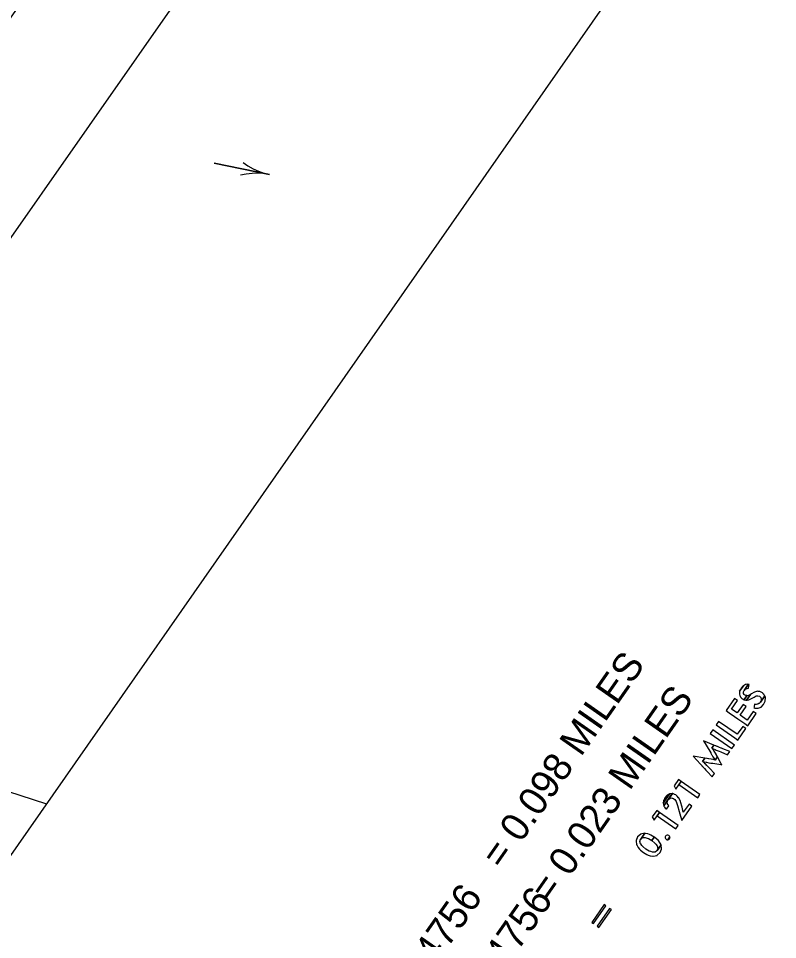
# Model space of a CAD drawing. Extents: x 1731327 to 1735374, y 884856 to 889832.
# Drawn here: x 1732222.4 to 1732491.1, y 885272.3 to 885598.5 of the extents above; entities that cross this region are included whole.
import ezdxf

# ---------------------------------------------------------------- set-up
doc = ezdxf.new("R2010")
doc.units = 0
for name, color, linetype in [('COGO Default Chain', 7, 'Continuous'), ('Exist Other Culture Area Outline', 7, 'Continuous'), ('Exist Other Culture Sign Text', 7, 'Continuous'), ('Exist Property Iron Pin CELL', 7, 'Continuous'), ('Exist Structure Minor Pipes RCP 24 Inch', 7, 'Continuous')]:
    doc.layers.add(name, color=color, linetype=linetype)

# ---------------------------------------------------------------- blocks, each defined once
blk = doc.blocks.new('EXIST HYDRO RIVER FLOW ARROW')
at = {"layer": 'COGO Default Chain'}
blk.add_line((0, 0), (0, 0), dxfattribs=at)
blk.add_lwpolyline([(0, 0.04575), (0.03775, 0.03), (0.07725, 0.01725), (0.118, 0.00775), (0.159, 0.0015), (0.2, 0), (-0.2, 0), (0.2, 0), (0.159, -0.0015), (0.118, -0.00775), (0.07725, -0.01725), (0.03775, -0.03), (0, -0.04575)], dxfattribs=at)

msp = doc.modelspace()

# ---------------------------------------------------------------- linework, layer by layer
at = {"layer": 'Exist Other Culture Area Outline'}
msp.add_lwpolyline([(1732238.91, 886072.74), (1731769.46, 885400.02), (1732118.14, 885156.7), (1732587.59, 885829.41)], close=True, dxfattribs=at)
at = {"layer": 'Exist Other Culture Sign Text'}
msp.add_lwpolyline([(1731775.28, 885408.36), (1732121.12, 885356.5), (1732232.4, 885320.42)], dxfattribs=at)
at = {"layer": 'Exist Property Iron Pin CELL'}
for points in [[(1732478.92, 885357.42), (1732479.22, 885357.24), (1732480.23, 885358.7), (1732479.83, 885358.73), (1732479.39, 885359), (1732479.36, 885359.02), (1732479.28, 885359.13), (1732479.08, 885359.43), (1732479.06, 885359.6), (1732479.04, 885359.85), (1732479.03, 885359.96), (1732479.05, 885360.03), (1732479.14, 885360.26), (1732479.25, 885360.55), (1732480.74, 885362.68), (1732480.56, 885362.71), (1732479.94, 885362.63), (1732479.79, 885362.62), (1732479, 885362.19), (1732477.67, 885360.28), (1732477.61, 885359.49), (1732477.59, 885359.27), (1732477.78, 885358.72), (1732477.84, 885358.53), (1732477.87, 885358.44), (1732477.9, 885358.37), (1732477.91, 885358.35), (1732477.96, 885358.29), (1732478.06, 885358.17), (1732478.14, 885358.08), (1732478.37, 885357.81), (1732478.45, 885357.71), (1732478.47, 885357.69)], [(1732477.72, 885360.39), (1732477.67, 885360.29), (1732479, 885362.19), (1732478.97, 885362.17), (1732478.17, 885361.32), (1732478.17, 885361.32)], [(1732480.38, 885361.29), (1732480.81, 885361.32), (1732480.91, 885362.05), (1732480.94, 885362.3), (1732480.99, 885362.64), (1732480.91, 885362.65), (1732480.89, 885362.66), (1732480.82, 885362.67), (1732480.74, 885362.68), (1732479.25, 885360.55), (1732479.69, 885361.05), (1732479.8, 885361.09), (1732479.83, 885361.1), (1732479.96, 885361.16), (1732480.23, 885361.28)], [(1732479.83, 885357.14), (1732480.05, 885357.1), (1732481.49, 885359.16), (1732481.07, 885358.9), (1732480.42, 885358.69), (1732480.24, 885358.7), (1732479.22, 885357.24), (1732479.39, 885357.21)], [(1732485.31, 885356.99), (1732485.05, 885356.45), (1732486.55, 885358.6), (1732486.51, 885358.71), (1732486.5, 885358.72), (1732486.49, 885358.74), (1732486.41, 885358.95), (1732486.36, 885359.01), (1732486.32, 885359.05), (1732486.12, 885359.25), (1732486.04, 885359.34), (1732485.98, 885359.41), (1732485.73, 885359.68), (1732485.53, 885359.78), (1732485.07, 885360.04), (1732484.86, 885360.16), (1732484.65, 885360.17), (1732484.24, 885360.21), (1732484.24, 885360.21), (1732483.92, 885360.24), (1732483.63, 885360.15), (1732482.93, 885359.94), (1732482.73, 885359.84), (1732481.9, 885359.4), (1732481.49, 885359.16), (1732480.05, 885357.1), (1732480.33, 885357.15), (1732480.93, 885357.25), (1732481.11, 885357.34), (1732481.93, 885357.71), (1732482.29, 885357.91), (1732482.85, 885358.22), (1732483.54, 885358.59), (1732483.8, 885358.63), (1732484.12, 885358.68), (1732484.65, 885358.52), (1732484.82, 885358.38), (1732485.09, 885358.14), (1732485.14, 885358.05), (1732485.2, 885357.93), (1732485.34, 885357.65), (1732485.34, 885357.55), (1732485.33, 885357.41), (1732485.32, 885357.07), (1732485.32, 885357.02)], [(1732479.47, 885348.82), (1732480.59, 885348.04), (1732483.58, 885352.33), (1732482.46, 885353.11), (1732480.33, 885350.06), (1732477.85, 885351.79), (1732479.98, 885354.84), (1732478.89, 885355.6), (1732476.76, 885352.56), (1732474.84, 885353.89), (1732476.97, 885356.94), (1732475.9, 885357.68), (1732472.91, 885353.4), (1732473.98, 885352.65), (1732475.89, 885351.31), (1732476.99, 885350.55)], [(1732485.25, 885354.66), (1732486.16, 885355.6), (1732486.75, 885356.8), (1732486.75, 885356.81), (1732486.79, 885357.88), (1732486.79, 885358.01), (1732486.55, 885358.6), (1732485.05, 885356.45), (1732484.57, 885355.93), (1732484.55, 885355.92), (1732484.51, 885355.9), (1732484.15, 885355.71), (1732484.01, 885355.64), (1732483.93, 885355.63), (1732483.58, 885355.6), (1732483.42, 885355.59), (1732483.33, 885355.61), (1732482.96, 885355.7), (1732482.82, 885354.89), (1732482.78, 885354.66), (1732482.73, 885354.39), (1732483.01, 885354.3), (1732483.06, 885354.29), (1732483.14, 885354.26), (1732483.33, 885354.21), (1732483.36, 885354.21), (1732483.36, 885354.21), (1732483.49, 885354.21), (1732484.14, 885354.22), (1732484.23, 885354.22), (1732485.24, 885354.65)], [(1732475.95, 885343.78), (1732477.07, 885342.99), (1732479.88, 885347.03), (1732478.76, 885347.81), (1732476.81, 885345.02), (1732470.25, 885349.6), (1732469.39, 885348.35)], [(1732467.27, 885345.32), (1732474.95, 885339.96), (1732475.82, 885341.21), (1732468.14, 885346.56)], [(1732468.61, 885336.44), (1732468.98, 885335.9), (1732469.8, 885337.08), (1732469.47, 885337.67), (1732469.47, 885337.67), (1732469.47, 885337.69), (1732469.11, 885338.32), (1732468.7, 885339.06), (1732468.7, 885339.07), (1732468.69, 885339.08), (1732468.64, 885339.15), (1732468.34, 885339.64), (1732468.32, 885339.66), (1732468.32, 885339.66), (1732468.3, 885339.68), (1732467.88, 885340.16), (1732468.6, 885341.19), (1732464.94, 885342.66), (1732467.08, 885339.02), (1732467.43, 885338.43), (1732467.44, 885338.41), (1732467.45, 885338.4), (1732467.46, 885338.38), (1732467.75, 885337.88), (1732467.8, 885337.8), (1732467.81, 885337.79), (1732467.81, 885337.79), (1732468.23, 885337.07), (1732468.61, 885336.45)], [(1732470.98, 885338.77), (1732473.42, 885337.77), (1732474.23, 885338.93), (1732471.78, 885339.91), (1732471.2, 885340.15), (1732471.19, 885340.15), (1732471.19, 885340.15), (1732470.56, 885340.4), (1732469.84, 885340.69), (1732469.84, 885340.69), (1732469.82, 885340.7), (1732469.74, 885340.73), (1732469.24, 885340.93), (1732469.22, 885340.94), (1732469.21, 885340.94), (1732469.19, 885340.95), (1732468.6, 885341.19), (1732467.88, 885340.16), (1732468.44, 885339.87), (1732468.46, 885339.86), (1732468.46, 885339.86), (1732468.48, 885339.85), (1732468.96, 885339.61), (1732469.04, 885339.58), (1732469.05, 885339.57), (1732469.05, 885339.57), (1732469.77, 885339.27), (1732470.39, 885339.02), (1732470.41, 885339.01)], [(1732466.17, 885331.88), (1732467.95, 885329.93), (1732468.75, 885331.08), (1732466.96, 885333.01), (1732466.54, 885333.47), (1732466.53, 885333.48), (1732466.53, 885333.48), (1732466.07, 885333.97), (1732465.55, 885334.54), (1732465.54, 885334.55), (1732465.54, 885334.55), (1732465.47, 885334.61), (1732465.1, 885334.99), (1732465.08, 885335.01), (1732465.07, 885335.01), (1732465.05, 885335.02), (1732464.57, 885335.42), (1732465.4, 885336.6), (1732461.21, 885337.33), (1732463.87, 885334.41), (1732464.3, 885333.94), (1732464.31, 885333.92), (1732464.32, 885333.92), (1732464.33, 885333.9), (1732464.7, 885333.5), (1732464.76, 885333.44), (1732464.76, 885333.43), (1732464.77, 885333.42), (1732465.29, 885332.85), (1732465.74, 885332.35), (1732465.75, 885332.34)], [(1732470.98, 885334.28), (1732471.4, 885334.21), (1732471.19, 885334.58), (1732469.8, 885337.08), (1732468.98, 885335.9), (1732468.35, 885336.06), (1732468.33, 885336.06), (1732467.64, 885336.21), (1732466.81, 885336.35), (1732466.81, 885336.35), (1732466.79, 885336.36), (1732466.7, 885336.37), (1732466.13, 885336.47), (1732466.1, 885336.48), (1732466.1, 885336.48), (1732466.07, 885336.48), (1732465.4, 885336.6), (1732464.57, 885335.42), (1732465.21, 885335.24), (1732465.23, 885335.24), (1732465.23, 885335.23), (1732465.26, 885335.23), (1732465.82, 885335.12), (1732465.92, 885335.1), (1732465.93, 885335.1), (1732465.93, 885335.1), (1732466.77, 885334.96), (1732467.48, 885334.85), (1732467.5, 885334.84), (1732468.16, 885334.74)], [(1732454.45, 885326.79), (1732455.11, 885325.61), (1732457.01, 885328.34), (1732456.01, 885329.03)], [(1732456.21, 885327.19), (1732462.82, 885322.58), (1732463.62, 885323.73), (1732457.01, 885328.34)], [(1732450.62, 885320.63), (1732450.82, 885319.7), (1732453.82, 885324.01), (1732452.91, 885323.91)], [(1732450.63, 885320.66), (1732450.62, 885320.63), (1732452.91, 885323.91), (1732452.89, 885323.91), (1732452.06, 885323.42), (1732451.96, 885323.36), (1732451.25, 885322.52), (1732451.25, 885322.52), (1732450.92, 885321.86), (1732450.78, 885321.57)], [(1732451.68, 885318.61), (1732451.81, 885318.5), (1732452.65, 885319.7), (1732452.52, 885319.81), (1732452.46, 885319.85), (1732452.45, 885319.87), (1732452.2, 885320.22), (1732452.19, 885320.27), (1732452.16, 885320.36), (1732452.03, 885320.77), (1732452.06, 885320.97), (1732452.12, 885321.35), (1732452.12, 885321.39), (1732452.52, 885322), (1732453.92, 885324.02), (1732453.82, 885324.01), (1732450.82, 885319.7), (1732450.86, 885319.63), (1732450.87, 885319.6), (1732450.89, 885319.59), (1732450.98, 885319.42), (1732451.03, 885319.34), (1732451.23, 885319.02), (1732451.27, 885318.95), (1732451.3, 885318.93), (1732451.61, 885318.66), (1732451.62, 885318.65)], [(1732456.75, 885316), (1732457.17, 885314.48), (1732460.75, 885319.62), (1732459.76, 885320.31), (1732457.72, 885317.39), (1732457.28, 885319.16), (1732456.71, 885321.16), (1732456.71, 885321.18), (1732456.11, 885322.5), (1732456.11, 885322.5), (1732456.09, 885322.53), (1732455.53, 885323.12), (1732455.24, 885323.42), (1732455.12, 885323.54), (1732455.05, 885323.57), (1732455.04, 885323.58), (1732454.66, 885323.74), (1732454.62, 885323.75), (1732454.55, 885323.78), (1732454.23, 885323.92), (1732454.23, 885323.92), (1732454.14, 885323.95), (1732453.98, 885324.02), (1732453.96, 885324.02), (1732453.92, 885324.02), (1732452.52, 885322), (1732452.58, 885322.05), (1732452.63, 885322.08), (1732453.05, 885322.39), (1732453.18, 885322.41), (1732453.65, 885322.49), (1732453.72, 885322.47), (1732453.76, 885322.46), (1732454.17, 885322.34), (1732454.19, 885322.33), (1732454.25, 885322.28), (1732454.38, 885322.19), (1732454.71, 885321.95), (1732455.18, 885321.23), (1732455.2, 885321.21), (1732455.73, 885319.76), (1732455.73, 885319.75), (1732456.28, 885317.73)], [(1732446.77, 885315.78), (1732447.43, 885314.6), (1732449.33, 885317.33), (1732448.33, 885318.02)], [(1732448.53, 885316.18), (1732455.14, 885311.57), (1732455.94, 885312.72), (1732449.33, 885317.33)], [(1732448.54, 885302.17), (1732449.52, 885303.11), (1732450.04, 885304.32), (1732450.07, 885304.39), (1732449.87, 885305.88), (1732448.45, 885303.83), (1732448.39, 885303.79), (1732448.37, 885303.77), (1732447.81, 885303.31), (1732446.86, 885303.26), (1732446.85, 885303.27), (1732446.85, 885303.26), (1732446.19, 885303.5), (1732446.18, 885303.5), (1732445.71, 885303.67), (1732445.68, 885303.68), (1732444.5, 885304.36), (1732444.49, 885304.37), (1732444.48, 885304.38), (1732443.44, 885305.24), (1732443.1, 885305.65), (1732443.09, 885305.66), (1732442.66, 885306.18), (1732442.64, 885306.2), (1732442.36, 885307.11), (1732442.62, 885307.84), (1732442.63, 885307.87), (1732442.66, 885307.93), (1732444.07, 885309.96), (1732442.63, 885309.63), (1732442.59, 885309.6), (1732441.58, 885308.67), (1732441.58, 885308.67), (1732441.03, 885307.36), (1732441.03, 885307.34), (1732441.23, 885305.89), (1732441.24, 885305.86), (1732441.24, 885305.85), (1732441.35, 885305.68), (1732441.8, 885304.98), (1732441.81, 885304.96), (1732442.19, 885304.37), (1732442.2, 885304.36), (1732442.59, 885304.02), (1732443.61, 885303.13), (1732443.62, 885303.12), (1732443.64, 885303.12), (1732444.82, 885302.46), (1732444.85, 885302.44), (1732445.27, 885302.2), (1732445.28, 885302.2), (1732445.99, 885302.04), (1732446, 885302.04), (1732446.79, 885301.86), (1732447, 885301.81), (1732447.01, 885301.81), (1732447.04, 885301.82), (1732448.52, 885302.16)], [(1732445.43, 885308.09), (1732446.6, 885307.41), (1732447.46, 885308.65), (1732446.28, 885309.31), (1732445.83, 885309.56), (1732445.82, 885309.57), (1732445.82, 885309.57), (1732445.13, 885309.73), (1732445.13, 885309.72), (1732445.11, 885309.73), (1732444.31, 885309.91), (1732444.31, 885309.91), (1732444.1, 885309.96), (1732444.1, 885309.96), (1732444.07, 885309.96), (1732442.66, 885307.93), (1732442.71, 885307.98), (1732442.73, 885307.99), (1732443.3, 885308.46), (1732444.25, 885308.5), (1732444.28, 885308.51), (1732444.92, 885308.27), (1732444.93, 885308.27)], [(1732448.47, 885303.9), (1732448.45, 885303.83), (1732449.87, 885305.88), (1732449.87, 885305.9), (1732449.87, 885305.92), (1732449.75, 885306.1), (1732449.31, 885306.78), (1732449.31, 885306.79), (1732448.92, 885307.4), (1732448.91, 885307.41), (1732448.54, 885307.73), (1732448.52, 885307.75), (1732447.49, 885308.63), (1732447.47, 885308.64), (1732447.46, 885308.65), (1732446.59, 885307.41), (1732446.61, 885307.4), (1732446.62, 885307.39), (1732447.66, 885306.53), (1732447.69, 885306.51), (1732448.01, 885306.12), (1732448.02, 885306.11), (1732448.47, 885305.58), (1732448.47, 885305.57), (1732448.75, 885304.66), (1732448.48, 885303.93)], [(1732451.96, 885307.7), (1732452.28, 885307.7), (1732452.96, 885308.67), (1732452.84, 885308.97), (1732452.62, 885309.2), (1732452.32, 885309.33), (1732451.99, 885309.34), (1732451.69, 885309.22), (1732451.45, 885308.99), (1732451.32, 885308.69), (1732451.31, 885308.37), (1732451.43, 885308.07), (1732451.66, 885307.83)], [(1732452.59, 885307.81), (1732452.82, 885308.04), (1732452.95, 885308.34), (1732452.96, 885308.67), (1732452.28, 885307.69)], [(1732425.37, 885278.42), (1732425.99, 885277.99), (1732430.37, 885284.28), (1732429.75, 885284.71)], [(1732427.27, 885277.09), (1732427.89, 885276.66), (1732432.28, 885282.95), (1732431.66, 885283.38)]]:
    msp.add_lwpolyline(points, close=True, dxfattribs=at)
at = {"layer": 'Exist Structure Minor Pipes RCP 24 Inch'}
msp.add_lwpolyline([(1732163.68, 885517.13), (1732205.03, 885502.1), (1732211.91, 885511.93), (1732213.12, 885511.49), (1732281.91, 885609.82), (1732280.69, 885610.26), (1732287.56, 885620.08), (1732246.22, 885635.13), (1732239.34, 885625.29), (1732238.37, 885625.65), (1732169.58, 885527.32), (1732170.56, 885526.96)], close=True, dxfattribs=at)

# ---------------------------------------------------------------- block references
at = {"layer": 'COGO Default Chain', "xscale": 49.99999999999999, "yscale": 50.000000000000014, "rotation": -11.672336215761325}
msp.add_blockref('EXIST HYDRO RIVER FLOW ARROW', (1732301.5, 885545.2), dxfattribs=at)

# ---------------------------------------------------------------- texts
at = {"layer": 'Exist Property Iron Pin CELL'}
for s, p in [('= 0.098 MILES', (1732393.62, 885296.84)), ('= 0.023 MILES', (1732410.85, 885284.82)), ('LENGTH ROADWAY TIP PROJECT B-4756', (1732235.64, 885070.46)), ('LENGTH STRUCTURE TIP PROJECT B-4756', (1732252.87, 885058.44))]:
    msp.add_text(s, height=10, rotation=55.0911, dxfattribs=at).set_placement(p)

doc.saveas('drawing.dxf')
